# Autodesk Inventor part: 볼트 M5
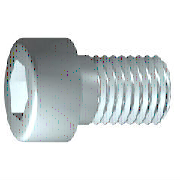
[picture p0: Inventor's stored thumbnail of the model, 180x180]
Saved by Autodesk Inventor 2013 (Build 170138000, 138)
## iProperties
IsCustomPart: 1
Created: 2012-02
Part Number: 볼트 M5
Material: 강철, 연강
Description: 6각머리 태핑 나사
Document SubType Name: Modeling
Standard: KS B 1003
Designer: mduedu
Standards Organization: KS
Language: ko-KR
Size Designation: M 5 x 16
Categories: <MemberInstance><Categories><Category DisplayName="조임쇠" InternalName="e4da775c-781d-43d5-af7c-5136215cf5a6" Mnemonic="FSTN"><Category DisplayName="볼트" InternalN
Density: 1 g/cm^3
Author: mduedu
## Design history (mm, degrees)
sketch "스케치1"
  geometry: L1 (-1.167, 0)-(16, 0); L2 (16, 0)-(16, 2.5); L3 (16, 2.5)-(2, 2.5); L4 (2, 2.5)-(1.509, 2.5); L5 (1.509, 2.5)-(0, 2.5); L6 (0, 2.5)-(0, 4.25); L7 (0, 4.25)-(-5, 4.25); L8 (-5, 4.25)-(-5, 2.309); L9 (-5, 2.309)-(-2.5, 2.309); L10 (-2.5, 2.309)-(-1.167, 0); L11 (-9.2, 0)-(20.2, 0) reference; L12 (0, -0.85)-(0, 5.1) reference; L13 (2, 2.5)-(0, 2.5)
  constraints: 22 end point, 6 parallel, 2 collinear, 2 perpendicular, 1 horizontal, 1 point on line
  dimensions: "d1" = 14 distance from line of L3.end L2 (= GEL); "d2" = 0.49086 distance of L4.end L3.end (computed from GAL); "d3" = 5 distance between parallel lines of L8 L6 (= KOH); "d4" = 2.5 distance of L8.end L9.end (= INTI); "d5" = 60 deg angle of L10 L1; "d6" = 5 diameter of L3 L1 (= GD); "d7" = 5 diameter of L5 L1 (= BDM); "d8" = 4.6188 diameter of L9 L1 (= 1.1547 x SW); "d9" = 8.5 diameter of L7 L1 (= KOD); "d26" = 16 distance between parallel lines of L12 L2 (= NLG)
revolve "본체" sketch "스케치1" stored, may be unused: angle "d10" = 90 deg
sketch "스케치2"
  geometry: L1 (0, -5.95)-(0, 5.95) reference; L2 (-5.95, 0)-(5.95, 0) reference; L3 (2.309, 0)-(1.155, -2); L4 (1.155, -2)-(-1.155, -2); L5 (-1.155, -2)-(-2.309, 0); L6 (-2.309, 0)-(-1.155, 2); L7 (-1.155, 2)-(1.155, 2); L8 (1.155, 2)-(2.309, 0); 2 further points
  constraints: 12 end point, 1 coincident, 1 horizontal alignment, 1 point on line, 12 other
extrude "슬롯" join sketch "스케치2" stored distance "d11" = 10; taper "d12" = 0 deg
workplane "Work Plane1"
fillet "Fillet2" dims "d30" = 0.1 (= R)
body "Solid1"
fillet "모깎기1" dims "d17" = 0.5 (= RR)
feature "스레드" dims "d13" = 14 (= GEL), "d14" = 0
chamfer "모따기1" distance "d15" = 0.49076 (= -0.5 x SPD + 0.5 x GD); stored, may be unused: second distance "d16" = 0.49076 (= GUL), angle "d27" = 45 deg
other parameters: "GD" = 5 (= NND) [user parameter; used in 2 equation terms], "NLG" = 16 [user parameter; used in 1 equation term], "GEL" = 14 [user parameter; used in 2 equation terms], "KOD" = 8.5 [user parameter; used in 1 equation term], "KOH" = 5 [user parameter; used in 1 equation term], "INTI" = 2.5 [user parameter; used in 1 equation term], "GAL" = 0.49076 (= 0.61345 x PTC) [user parameter; used in 1 equation term], "GUL" = 0.49076 (= 0.61345 x PTC) [user parameter; used in 1 equation term], "BDM" = 5 (= NND) [user parameter; used in 1 equation term], "SW" = 4 [user parameter; used in 2 equation terms], "RR" = 0.5 [user parameter; used in 1 equation term], "SPD" = 4.01848 (= NND - 1.2269 x PTC) [user parameter; used in 1 equation term], "d19" = 0, "d28" = 0, "d29" = 0, "R" = 0.1 [user parameter; used in 1 equation term], "PHH" = 0.2 [user parameter], "GD1" = 4.01848 (= THREADDIA - 1.2269 x PTC) [user parameter], "THREADDIA" = 5 [user parameter; used in 1 equation term], "FAWI" = 45 deg [user parameter], "TPU" = 12.5 (computed from PTC) [user parameter], "PTC" = 0.8 [user parameter; used in 5 equation terms], "NND" = 5 [user parameter; used in 3 equation terms], "TOA" = 30 deg [user parameter], "E0" = 4.62 (= 1.155 x SW) [user parameter]
